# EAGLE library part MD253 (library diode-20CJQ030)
MSytems mDOC H3 Embedded Flash Drive (EFD) featuring Embedded TrueFFS® Flash Management Software mDOC H3 is an Embedded Flash Drive (EFD) designed for mobile handsets and consumer electronics devices. mDOC H3 is the new generation of the successful msystems mDOC product family, enabling tens of millions of handsets and other mobile devices since the year 2000. mDOC H3 is a hybrid device combining an embedded thin flash controller and standard flash memory. In addition to the high reliability and high system performance offered by the current mDOC family of products, mDOC H3 offers plug-and-play integration, support for multiple NAND technologies and more features such as advanced power management schemes. mDOC H3 uses the most advanced Multi-Level Cell (MLC) and binary (SLC) NAND flash technologies, enhanced by msystems proprietary TrueFFS embedded flash management software running as firmware on the flash controller. The breakthrough in performance, size, cost and design makes mDOC H3 the ideal solution for mobile handsets and consumer electronics manufacturers who require easy integration, fast time to market, high-capacity, small form factor, high-performance and most importantly, high reliable storage. Please send any comments to: messi@users.sourceforge.net
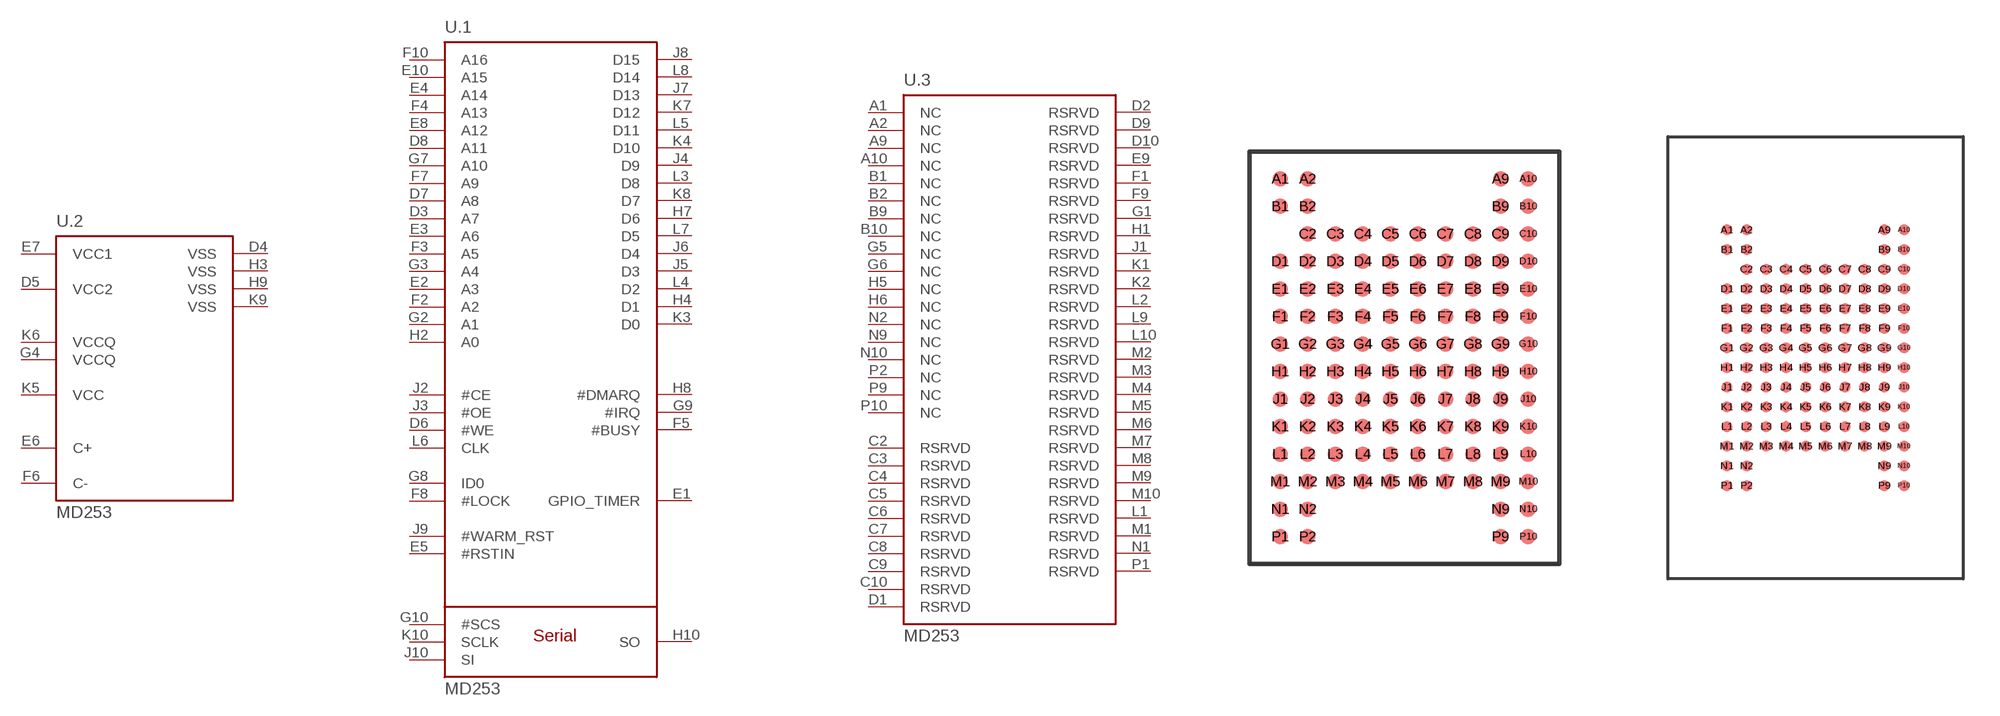
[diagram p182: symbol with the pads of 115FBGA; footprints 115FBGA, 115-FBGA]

Designator prefix U; gates .1=MD2533_MD2534 .2=MD2533_MD2534_PWR .3=MD2533_MD2534_NC

## MD2533-D**G-X-P  [115FBGA]
A1  .3:NC  nc
A2  .3:NC  nc
A9  .3:NC  nc
A10  .3:NC  nc
B1  .3:NC  nc
B2  .3:NC  nc
B9  .3:NC  nc
B10  .3:NC  nc
C2  .3:RSRVD  nc
C3  .3:RSRVD  nc
C4  .3:RSRVD  nc
C5  .3:RSRVD  nc
C6  .3:RSRVD  nc
C7  .3:RSRVD  nc
C8  .3:RSRVD  nc
C9  .3:RSRVD  nc
C10  .3:RSRVD  nc
D1  .3:RSRVD  nc
D2  .3:RSRVD  nc
D3  .1:A7  in
D4  .2:VSS  pwr
D5  .2:VCC2  pwr
D6  .1:#WE  in
D7  .1:A8  in
D8  .1:A11  in
D9  .3:RSRVD  nc
D10  .3:RSRVD  nc
E1  .1:GPIO_TIMER
E2  .1:A3  in
E3  .1:A6  in
E4  .1:A14  in
E5  .1:#RSTIN  in
E6  .2:C+  pwr
E7  .2:VCC1  pwr
E8  .1:A12  in
E9  .3:RSRVD  nc
E10  .1:A15  in
F1  .3:RSRVD  nc
F2  .1:A2  in
F3  .1:A5  in
F4  .1:A13  in
F5  .1:#BUSY  out
F6  .2:C-  pwr
F7  .1:A9  in
F8  .1:#LOCK  in
F9  .3:RSRVD  nc
F10  .1:A16  in
G1  .3:RSRVD  nc
G2  .1:A1  in
G3  .1:A4  in
G4  .2:VCCQ  pwr
G5  .3:NC  nc
G6  .3:NC  nc
G7  .1:A10  in
G8  .1:ID0  in
G9  .1:#IRQ  out
G10  .1:#SCS
H1  .3:RSRVD  nc
H2  .1:A0  in
H3  .2:VSS  pwr
H4  .1:D1
H5  .3:NC  nc
H6  .3:NC  nc
H7  .1:D6
H8  .1:#DMARQ  out
H9  .2:VSS  pwr
H10  .1:SO
J1  .3:RSRVD  nc
J2  .1:#CE  in
J3  .1:#OE  in
J4  .1:D9
J5  .1:D3
J6  .1:D4
J7  .1:D13
J8  .1:D15
J9  .1:#WARM_RST  in
J10  .1:SI
K1  .3:RSRVD  nc
K2  .3:RSRVD  nc
K3  .1:D0
K4  .1:D10
K5  .2:VCC  pwr
K6  .2:VCCQ  pwr
K7  .1:D12
K8  .1:D7
K9  .2:VSS  pwr
K10  .1:SCLK
L1  .3:RSRVD  nc
L2  .3:RSRVD  nc
L3  .1:D8
L4  .1:D2
L5  .1:D11
L6  .1:CLK  in
L7  .1:D5
L8  .1:D14
L9  .3:RSRVD  nc
L10  .3:RSRVD  nc
M1  .3:RSRVD  nc
M2  .3:RSRVD  nc
M3  .3:RSRVD  nc
M4  .3:RSRVD  nc
M5  .3:RSRVD  nc
M6  .3:RSRVD  nc
M7  .3:RSRVD  nc
M8  .3:RSRVD  nc
M9  .3:RSRVD  nc
M10  .3:RSRVD  nc
N1  .3:RSRVD  nc
N2  .3:NC  nc
N9  .3:NC  nc
N10  .3:NC  nc
P1  .3:RSRVD  nc
P2  .3:NC  nc
P9  .3:NC  nc
P10  .3:NC  nc

## MD2534-D**G-X-P  [115-FBGA]
Pads as for 115FBGA

## Footprint 115FBGA (pad centres in mm)
smd 0.45 x 0.45: A1 -3.6,5.2; A2 -2.8,5.2; A9 2.8,5.2; A10 3.6,5.2; B1 -3.6,4.4; B2 -2.8,4.4; B9 2.8,4.4; B10 3.6,4.4; C2 -2.8,3.6; C3 -2,3.6; C4 -1.2,3.6; C5 -0.4,3.6; C6 0.4,3.6; C7 1.2,3.6; C8 2,3.6; C9 2.8,3.6; C10 3.6,3.6; D1 -3.6,2.8; D2 -2.8,2.8; D3 -2,2.8; D4 -1.2,2.8; D5 -0.4,2.8; D6 0.4,2.8; D7 1.2,2.8; D8 2,2.8; D9 2.8,2.8; D10 3.6,2.8; E1 -3.6,2; E2 -2.8,2; E3 -2,2; E4 -1.2,2; E5 -0.4,2; E6 0.4,2; E7 1.2,2; E8 2,2; E9 2.8,2; E10 3.6,2; F1 -3.6,1.2; F2 -2.8,1.2; F3 -2,1.2; F4 -1.2,1.2; F5 -0.4,1.2; F6 0.4,1.2; F7 1.2,1.2; F8 2,1.2; F9 2.8,1.2; F10 3.6,1.2; G1 -3.6,0.4; G2 -2.8,0.4; G3 -2,0.4; G4 -1.2,0.4; G5 -0.4,0.4; G6 0.4,0.4; G7 1.2,0.4; G8 2,0.4; G9 2.8,0.4; G10 3.6,0.4; H1 -3.6,-0.4; H2 -2.8,-0.4; H3 -2,-0.4; H4 -1.2,-0.4; H5 -0.4,-0.4; H6 0.4,-0.4; H7 1.2,-0.4; H8 2,-0.4; H9 2.8,-0.4; H10 3.6,-0.4; J1 -3.6,-1.2; J2 -2.8,-1.2; J3 -2,-1.2; J4 -1.2,-1.2; J5 -0.4,-1.2; J6 0.4,-1.2; J7 1.2,-1.2; J8 2,-1.2; J9 2.8,-1.2; J10 3.6,-1.2; K1 -3.6,-2; K2 -2.8,-2; K3 -2,-2; K4 -1.2,-2; K5 -0.4,-2; K6 0.4,-2; K7 1.2,-2; K8 2,-2; K9 2.8,-2; K10 3.6,-2; L1 -3.6,-2.8; L2 -2.8,-2.8; L3 -2,-2.8; L4 -1.2,-2.8; L5 -0.4,-2.8; L6 0.4,-2.8; L7 1.2,-2.8; L8 2,-2.8; L9 2.8,-2.8; L10 3.6,-2.8; M1 -3.6,-3.6; M2 -2.8,-3.6; M3 -2,-3.6; M4 -1.2,-3.6; M5 -0.4,-3.6; M6 0.4,-3.6; M7 1.2,-3.6; M8 2,-3.6; M9 2.8,-3.6; M10 3.6,-3.6; N1 -3.6,-4.4; N2 -2.8,-4.4; N9 2.8,-4.4; N10 3.6,-4.4; P1 -3.6,-5.2; P2 -2.8,-5.2; P9 2.8,-5.2; P10 3.6,-5.2

## Footprint 115-FBGA (pad centres in mm)
M-Systems 115 FBGA for mDOC H3 4Gb (512MB)/8Gb (1GB)/ 16Gb (2GB)
smd 0.45 x 0.45: A1 -3.6,5.2; A2 -2.8,5.2; A9 2.8,5.2; A10 3.6,5.2; B1 -3.6,4.4; B2 -2.8,4.4; B9 2.8,4.4; B10 3.6,4.4; C2 -2.8,3.6; C3 -2,3.6; C4 -1.2,3.6; C5 -0.4,3.6; C6 0.4,3.6; C7 1.2,3.6; C8 2,3.6; C9 2.8,3.6; C10 3.6,3.6; D1 -3.6,2.8; D2 -2.8,2.8; D3 -2,2.8; D4 -1.2,2.8; D5 -0.4,2.8; D6 0.4,2.8; D7 1.2,2.8; D8 2,2.8; D9 2.8,2.8; D10 3.6,2.8; E1 -3.6,2; E2 -2.8,2; E3 -2,2; E4 -1.2,2; E5 -0.4,2; E6 0.4,2; E7 1.2,2; E8 2,2; E9 2.8,2; E10 3.6,2; F1 -3.6,1.2; F2 -2.8,1.2; F3 -2,1.2; F4 -1.2,1.2; F5 -0.4,1.2; F6 0.4,1.2; F7 1.2,1.2; F8 2,1.2; F9 2.8,1.2; F10 3.6,1.2; G1 -3.6,0.4; G2 -2.8,0.4; G3 -2,0.4; G4 -1.2,0.4; G5 -0.4,0.4; G6 0.4,0.4; G7 1.2,0.4; G8 2,0.4; G9 2.8,0.4; G10 3.6,0.4; H1 -3.6,-0.4; H2 -2.8,-0.4; H3 -2,-0.4; H4 -1.2,-0.4; H5 -0.4,-0.4; H6 0.4,-0.4; H7 1.2,-0.4; H8 2,-0.4; H9 2.8,-0.4; H10 3.6,-0.4; J1 -3.6,-1.2; J2 -2.8,-1.2; J3 -2,-1.2; J4 -1.2,-1.2; J5 -0.4,-1.2; J6 0.4,-1.2; J7 1.2,-1.2; J8 2,-1.2; J9 2.8,-1.2; J10 3.6,-1.2; K1 -3.6,-2; K2 -2.8,-2; K3 -2,-2; K4 -1.2,-2; K5 -0.4,-2; K6 0.4,-2; K7 1.2,-2; K8 2,-2; K9 2.8,-2; K10 3.6,-2; L1 -3.6,-2.8; L2 -2.8,-2.8; L3 -2,-2.8; L4 -1.2,-2.8; L5 -0.4,-2.8; L6 0.4,-2.8; L7 1.2,-2.8; L8 2,-2.8; L9 2.8,-2.8; L10 3.6,-2.8; M1 -3.6,-3.6; M2 -2.8,-3.6; M3 -2,-3.6; M4 -1.2,-3.6; M5 -0.4,-3.6; M6 0.4,-3.6; M7 1.2,-3.6; M8 2,-3.6; M9 2.8,-3.6; M10 3.6,-3.6; N1 -3.6,-4.4; N2 -2.8,-4.4; N9 2.8,-4.4; N10 3.6,-4.4; P1 -3.6,-5.2; P2 -2.8,-5.2; P9 2.8,-5.2; P10 3.6,-5.2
